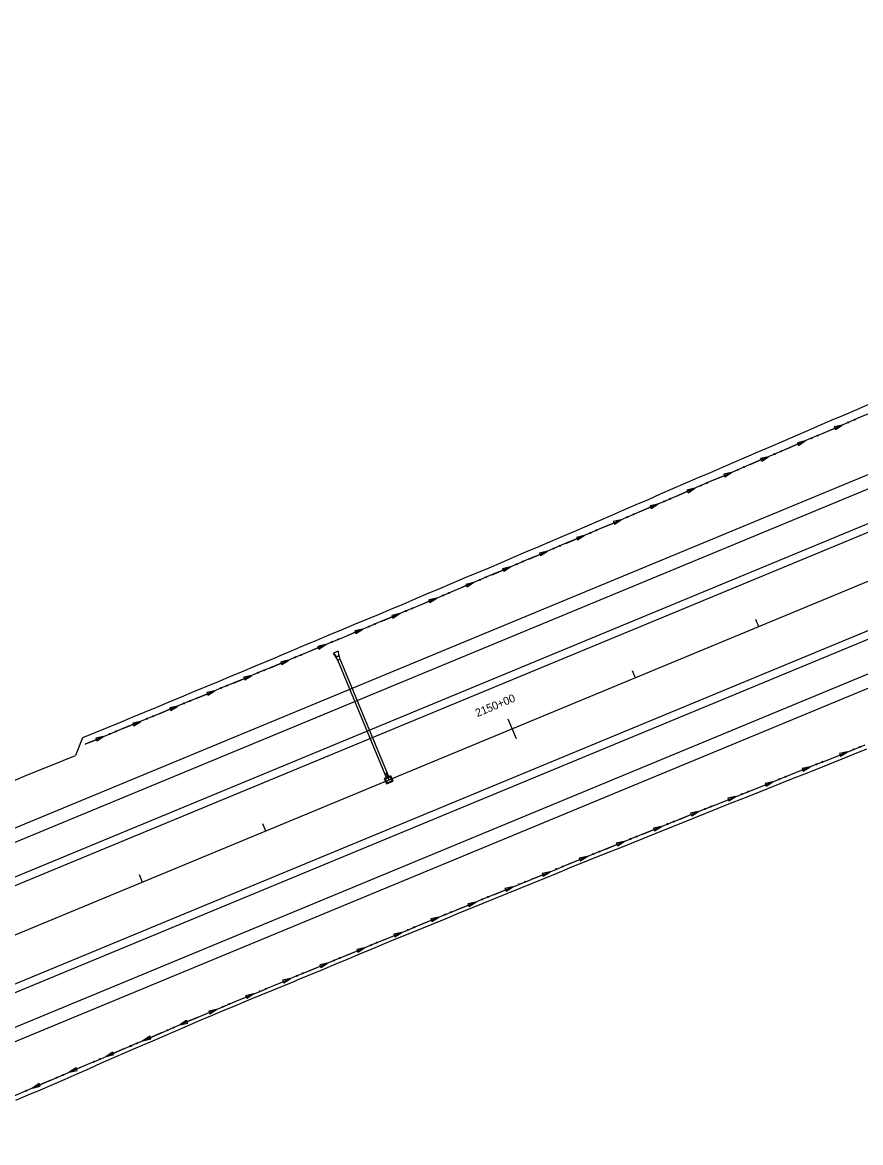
# Model space of a CAD drawing. Extents: x 1611108 to 1749517, y 619561 to 797725.
# Drawn here: x 1720490 to 1721119, y 767471 to 768311 of the extents above; entities that cross this region are included whole.
import ezdxf

# ---------------------------------------------------------------- set-up
doc = ezdxf.new("R2010")
doc.units = 0
for name, color, linetype in [('R_Ditch', 7, 'Continuous'), ('R_Drainage', 7, 'Continuous'), ('R_Horz Alg', 7, 'Continuous'), ('R_Horz Alg Stationing', 7, 'Continuous'), ('R_Proposed Const Limits', 7, 'Continuous'), ('R_Proposed Road', 7, 'Continuous')]:
    doc.layers.add(name, color=color, linetype=linetype)

msp = doc.modelspace()

# ---------------------------------------------------------------- linework, layer by layer
at = {"layer": 'R_Ditch'}
for p, q in [((1721104.89, 768009.2), (1721098.96, 768007.81)), ((1721099.79, 768005.87), (1721104.89, 768009.2)), ((1721098.96, 768007.81), (1721099.79, 768005.87)), ((1721077.28, 767997.38), (1721071.34, 767995.99)), ((1721071.34, 767995.99), (1721072.18, 767994.04)), ((1721072.18, 767994.04), (1721077.28, 767997.38)), ((1721049.66, 767985.55), (1721043.73, 767984.16)), ((1721043.73, 767984.16), (1721044.57, 767982.21)), ((1721044.57, 767982.21), (1721049.66, 767985.55)), ((1721022.05, 767973.72), (1721016.12, 767972.33)), ((1721016.12, 767972.33), (1721016.95, 767970.39)), ((1721016.95, 767970.39), (1721022.05, 767973.72)), ((1720994.44, 767961.89), (1720988.51, 767960.5)), ((1720988.51, 767960.5), (1720989.34, 767958.56)), ((1720989.34, 767958.56), (1720994.44, 767961.89)), ((1720966.83, 767950.07), (1720960.9, 767948.68)), ((1720961.73, 767946.73), (1720966.83, 767950.07)), ((1720960.9, 767948.68), (1720961.73, 767946.73)), ((1720939.22, 767938.24), (1720933.28, 767936.86)), ((1720933.28, 767936.86), (1720934.12, 767934.91)), ((1720934.12, 767934.91), (1720939.22, 767938.24)), ((1720911.59, 767926.44), (1720905.66, 767925.06)), ((1720905.66, 767925.06), (1720906.49, 767923.12)), ((1720906.49, 767923.12), (1720911.59, 767926.44)), ((1720883.96, 767914.68), (1720878.02, 767913.3)), ((1720878.02, 767913.3), (1720878.85, 767911.36)), ((1720878.85, 767911.36), (1720883.96, 767914.68)), ((1720856.31, 767902.94), (1720850.37, 767901.57)), ((1720850.37, 767901.57), (1720851.19, 767899.62)), ((1720851.19, 767899.62), (1720856.31, 767902.94)), ((1720828.64, 767891.23), (1720822.7, 767889.87)), ((1720823.53, 767887.92), (1720828.64, 767891.23)), ((1720822.7, 767889.87), (1720823.53, 767887.92)), ((1720800.97, 767879.55), (1720795.03, 767878.2)), ((1720795.03, 767878.2), (1720795.85, 767876.25)), ((1720795.85, 767876.25), (1720800.97, 767879.55)), ((1720773.28, 767867.9), (1720767.34, 767866.56)), ((1720767.34, 767866.56), (1720768.16, 767864.61)), ((1720768.16, 767864.61), (1720773.28, 767867.9)), ((1720745.58, 767856.29), (1720739.64, 767854.94)), ((1720739.64, 767854.94), (1720740.46, 767852.99)), ((1720740.46, 767852.99), (1720745.58, 767856.29)), ((1720717.87, 767844.7), (1720711.92, 767843.36)), ((1720711.92, 767843.36), (1720712.74, 767841.41)), ((1720712.74, 767841.41), (1720717.87, 767844.7)), ((1720690.14, 767833.14), (1720684.2, 767831.81)), ((1720684.2, 767831.81), (1720685.01, 767829.86)), ((1720685.01, 767829.86), (1720690.14, 767833.14)), ((1720662.41, 767821.61), (1720656.46, 767820.29)), ((1720656.46, 767820.29), (1720657.27, 767818.33)), ((1720657.27, 767818.33), (1720662.41, 767821.61)), ((1720634.66, 767810.11), (1720628.71, 767808.8)), ((1720628.71, 767808.8), (1720629.52, 767806.84)), ((1720629.52, 767806.84), (1720634.66, 767810.11)), ((1720606.89, 767798.64), (1720600.94, 767797.33)), ((1720601.75, 767795.38), (1720606.89, 767798.64)), ((1720600.94, 767797.33), (1720601.75, 767795.38)), ((1720579.12, 767787.2), (1720573.17, 767785.9)), ((1720573.17, 767785.9), (1720573.97, 767783.94)), ((1720573.97, 767783.94), (1720579.12, 767787.2)), ((1720551.33, 767775.8), (1720545.38, 767774.5)), ((1720545.38, 767774.5), (1720546.18, 767772.54)), ((1720546.18, 767772.54), (1720551.33, 767775.8)), ((1721108.82, 767764.25), (1721102.85, 767763.01)), ((1721102.85, 767763.01), (1721103.64, 767761.04)), ((1721103.64, 767761.04), (1721108.82, 767764.25)), ((1721080.93, 767753.09), (1721074.97, 767751.85)), ((1721074.97, 767751.85), (1721075.75, 767749.88)), ((1721075.75, 767749.88), (1721080.93, 767753.09)), ((1721053.04, 767741.93), (1721047.08, 767740.69)), ((1721047.08, 767740.69), (1721047.86, 767738.72)), ((1721047.86, 767738.72), (1721053.04, 767741.93)), ((1721025.16, 767730.77), (1721019.19, 767729.52)), ((1721019.19, 767729.52), (1721019.98, 767727.55)), ((1721019.98, 767727.55), (1721025.16, 767730.77)), ((1720997.28, 767719.58), (1720991.32, 767718.32)), ((1720991.32, 767718.32), (1720992.11, 767716.36)), ((1720992.11, 767716.36), (1720997.28, 767719.58)), ((1720969.42, 767708.35), (1720963.46, 767707.09)), ((1720963.46, 767707.09), (1720964.25, 767705.13)), ((1720964.25, 767705.13), (1720969.42, 767708.35)), ((1720941.57, 767697.1), (1720935.61, 767695.83)), ((1720935.61, 767695.83), (1720936.4, 767693.87)), ((1720936.4, 767693.87), (1720941.57, 767697.1)), ((1720913.73, 767685.82), (1720907.77, 767684.55)), ((1720907.77, 767684.55), (1720908.57, 767682.59)), ((1720908.57, 767682.59), (1720913.73, 767685.82)), ((1720885.9, 767674.51), (1720879.94, 767673.23)), ((1720879.94, 767673.23), (1720880.74, 767671.27)), ((1720880.74, 767671.27), (1720885.9, 767674.51)), ((1720858.09, 767663.17), (1720852.13, 767661.88)), ((1720852.13, 767661.88), (1720852.93, 767659.92)), ((1720852.93, 767659.92), (1720858.09, 767663.17)), ((1720830.28, 767651.8), (1720824.33, 767650.5)), ((1720824.33, 767650.5), (1720825.13, 767648.55)), ((1720825.13, 767648.55), (1720830.28, 767651.8)), ((1720802.49, 767640.4), (1720796.54, 767639.09)), ((1720796.54, 767639.09), (1720797.35, 767637.14)), ((1720797.35, 767637.14), (1720802.49, 767640.4)), ((1720774.72, 767628.97), (1720768.76, 767627.66)), ((1720768.76, 767627.66), (1720769.57, 767625.7)), ((1720769.57, 767625.7), (1720774.72, 767628.97)), ((1720746.95, 767617.5), (1720741, 767616.19)), ((1720741, 767616.19), (1720741.81, 767614.23)), ((1720741.81, 767614.23), (1720746.95, 767617.5)), ((1720719.2, 767606.01), (1720713.25, 767604.69)), ((1720714.06, 767602.74), (1720719.2, 767606.01)), ((1720713.25, 767604.69), (1720714.06, 767602.74)), ((1720691.46, 767594.49), (1720685.51, 767593.16)), ((1720685.51, 767593.16), (1720686.32, 767591.21)), ((1720686.32, 767591.21), (1720691.46, 767594.49)), ((1720663.73, 767582.94), (1720657.78, 767581.6)), ((1720657.78, 767581.6), (1720658.6, 767579.65)), ((1720658.6, 767579.65), (1720663.73, 767582.94)), ((1720636.01, 767571.36), (1720630.07, 767570.02)), ((1720630.07, 767570.02), (1720630.89, 767568.07)), ((1720630.89, 767568.07), (1720636.01, 767571.36)), ((1720613.48, 767563.01), (1720608.38, 767559.68)), ((1720608.38, 767559.68), (1720614.31, 767561.06)), ((1720614.31, 767561.06), (1720613.48, 767563.01)), ((1720585.86, 767551.21), (1720580.76, 767547.87)), ((1720580.76, 767547.87), (1720586.69, 767549.26)), ((1720586.69, 767549.26), (1720585.86, 767551.21)), ((1720558.25, 767539.38), (1720553.15, 767536.04)), ((1720559.08, 767537.43), (1720558.25, 767539.38)), ((1720553.15, 767536.04), (1720559.08, 767537.43)), ((1720530.64, 767527.55), (1720525.54, 767524.22)), ((1720525.54, 767524.22), (1720531.47, 767525.61)), ((1720531.47, 767525.61), (1720530.64, 767527.55)), ((1720503.02, 767515.72), (1720497.93, 767512.39)), ((1720497.93, 767512.39), (1720503.86, 767513.78)), ((1720503.86, 767513.78), (1720503.02, 767515.72))]:
    msp.add_line(p, q, dxfattribs=at)
for points in [[(1721127.19, 768018.76), (1721118, 768014.82), (1721108.8, 768010.88), (1721099.61, 768006.94), (1721090.42, 768003.01), (1721081.23, 767999.07), (1721072.03, 767995.13), (1721062.84, 767991.19), (1721053.65, 767987.25), (1721044.45, 767983.32), (1721035.26, 767979.38), (1721026.07, 767975.44), (1721016.88, 767971.5), (1721007.68, 767967.57), (1720998.49, 767963.63), (1720989.3, 767959.69), (1720980.1, 767955.75), (1720970.91, 767951.82), (1720961.72, 767947.88), (1720952.53, 767943.94), (1720943.33, 767940), (1720934.14, 767936.07), (1720924.94, 767932.14), (1720915.74, 767928.21), (1720906.54, 767924.29), (1720897.34, 767920.37), (1720888.14, 767916.46), (1720878.94, 767912.54), (1720869.73, 767908.64), (1720860.53, 767904.73), (1720851.32, 767900.83), (1720842.11, 767896.93), (1720832.9, 767893.03), (1720823.69, 767889.14), (1720814.48, 767885.25), (1720805.26, 767881.36), (1720796.05, 767877.48), (1720786.83, 767873.6), (1720777.61, 767869.72), (1720768.39, 767865.85), (1720759.17, 767861.98), (1720749.95, 767858.11), (1720740.73, 767854.25), (1720731.5, 767850.39), (1720722.27, 767846.54), (1720713.04, 767842.68), (1720703.82, 767838.83), (1720694.58, 767834.99), (1720685.35, 767831.15), (1720683.46, 767830.36), (1720676.12, 767827.31), (1720666.88, 767823.47), (1720657.65, 767819.64), (1720648.41, 767815.81), (1720639.17, 767811.98), (1720629.93, 767808.16), (1720620.69, 767804.34), (1720611.45, 767800.52), (1720602.2, 767796.71), (1720592.96, 767792.9), (1720583.71, 767789.09), (1720574.46, 767785.29), (1720565.21, 767781.49), (1720555.96, 767777.69), (1720546.71, 767773.9), (1720537.45, 767770.11)], [(1721091.1, 768003.3), (1721099.61, 768006.94), (1721104.89, 768009.2)], [(1721118.68, 768015.11), (1721118.71, 768015.12)], [(1721091.06, 768003.28), (1721091.1, 768003.3)], [(1721063.45, 767991.45), (1721063.49, 767991.47)], [(1721063.49, 767991.47), (1721072.03, 767995.13), (1721077.28, 767997.38)], [(1721035.88, 767979.64), (1721044.45, 767983.32), (1721049.66, 767985.55)], [(1721035.84, 767979.63), (1721035.88, 767979.64)], [(1721008.23, 767967.8), (1721008.26, 767967.82)], [(1721008.26, 767967.82), (1721016.88, 767971.5), (1721022.05, 767973.72)], [(1720980.65, 767955.99), (1720989.3, 767959.69), (1720994.44, 767961.89)], [(1720953.04, 767944.16), (1720961.72, 767947.88), (1720966.83, 767950.07)], [(1720980.62, 767955.97), (1720980.65, 767955.99)], [(1720953.01, 767944.15), (1720953.04, 767944.16)], [(1720925.42, 767932.35), (1720934.14, 767936.07), (1720939.22, 767938.24)], [(1720897.79, 767920.56), (1720906.54, 767924.29), (1720911.59, 767926.44)], [(1720925.39, 767932.33), (1720925.42, 767932.35)], [(1720897.76, 767920.55), (1720897.79, 767920.56)], [(1720870.11, 767908.8), (1720870.15, 767908.81)], [(1720870.15, 767908.81), (1720878.94, 767912.54), (1720883.96, 767914.68)], [(1720842.49, 767897.09), (1720851.32, 767900.83), (1720856.31, 767902.94)], [(1720814.83, 767885.4), (1720823.69, 767889.14), (1720828.64, 767891.23)], [(1720842.46, 767897.07), (1720842.49, 767897.09)], [(1720814.79, 767885.38), (1720814.83, 767885.39)], [(1720787.11, 767873.72), (1720787.14, 767873.73)], [(1720787.14, 767873.73), (1720796.05, 767877.48), (1720800.97, 767879.55)], [(1720759.45, 767862.1), (1720768.39, 767865.85), (1720773.28, 767867.9)], [(1720759.42, 767862.08), (1720759.45, 767862.1)], [(1720731.71, 767850.48), (1720731.74, 767850.49)], [(1720731.74, 767850.49), (1720740.73, 767854.25), (1720745.58, 767856.29)], [(1720704.03, 767838.92), (1720713.04, 767842.68), (1720717.87, 767844.7)], [(1720676.29, 767827.38), (1720683.46, 767830.36), (1720685.35, 767831.15), (1720690.14, 767833.14)], [(1720703.99, 767838.91), (1720704.02, 767838.92)], [(1720676.26, 767827.36), (1720676.29, 767827.38)], [(1720648.52, 767815.85), (1720648.55, 767815.86)], [(1720648.55, 767815.86), (1720657.65, 767819.64), (1720662.41, 767821.61)], [(1720620.79, 767804.38), (1720629.93, 767808.16), (1720634.66, 767810.11)], [(1720593.03, 767792.93), (1720602.2, 767796.71), (1720606.89, 767798.64)], [(1720620.76, 767804.37), (1720620.79, 767804.38)], [(1720592.99, 767792.91), (1720593.03, 767792.93)], [(1720565.21, 767781.49), (1720565.21, 767781.49), (1720565.24, 767781.5)], [(1720565.24, 767781.5), (1720574.46, 767785.29), (1720579.12, 767787.2)], [(1720537.45, 767770.11), (1720546.71, 767773.9), (1720551.33, 767775.8)], [(1720622.18, 767565.56), (1720629.25, 767568.53), (1720631.4, 767569.43), (1720636.4, 767571.52), (1720640.62, 767573.29), (1720649.85, 767577.15), (1720659.08, 767581), (1720668.31, 767584.85), (1720677.54, 767588.7), (1720686.77, 767592.54), (1720693.51, 767595.35), (1720696, 767596.38), (1720705.24, 767600.22), (1720714.47, 767604.05), (1720723.71, 767607.88), (1720732.95, 767611.71), (1720742.19, 767615.54), (1720751.43, 767619.36), (1720752.71, 767619.89), (1720760.67, 767623.17), (1720768.03, 767626.21), (1720769.92, 767626.99), (1720779.16, 767630.8), (1720788.41, 767634.61), (1720797.66, 767638.41), (1720806.91, 767642.21), (1720816.16, 767646.01), (1720825.41, 767649.8), (1720834.66, 767653.59), (1720843.92, 767657.38), (1720853.18, 767661.17), (1720862.43, 767664.95), (1720871.69, 767668.72), (1720880.95, 767672.5), (1720890.22, 767676.27), (1720899.48, 767680.04), (1720908.74, 767683.8), (1720918.01, 767687.56), (1720927.28, 767691.32), (1720936.55, 767695.07), (1720945.82, 767698.82), (1720955.09, 767702.57), (1720964.36, 767706.32), (1720973.64, 767710.06), (1720982.91, 767713.79), (1720992.19, 767717.53), (1721001.47, 767721.26), (1721010.75, 767724.99), (1721020.03, 767728.71), (1721029.31, 767732.43), (1721038.59, 767736.15), (1721047.88, 767739.87), (1721057.16, 767743.58), (1721066.45, 767747.3), (1721075.73, 767751.01), (1721085.02, 767754.73), (1721094.3, 767758.45), (1721103.59, 767762.16), (1721112.87, 767765.88), (1721122.16, 767769.59)], [(1721094.86, 767758.67), (1721094.89, 767758.68)], [(1721094.89, 767758.68), (1721103.59, 767762.16), (1721108.82, 767764.25)], [(1721067, 767747.52), (1721075.73, 767751.01), (1721080.93, 767753.09)], [(1721039.12, 767736.36), (1721047.88, 767739.87), (1721053.04, 767741.93)], [(1721066.97, 767747.51), (1721067, 767747.52)], [(1721039.08, 767736.34), (1721039.12, 767736.36)], [(1721011.2, 767725.17), (1721011.23, 767725.18)], [(1721011.23, 767725.18), (1721020.03, 767728.71), (1721025.16, 767730.77)], [(1720983.36, 767713.98), (1720992.19, 767717.53), (1720997.28, 767719.58)], [(1720955.51, 767702.74), (1720964.36, 767706.32), (1720969.42, 767708.35)], [(1720983.33, 767713.96), (1720983.36, 767713.98)], [(1720955.47, 767702.73), (1720955.51, 767702.74)], [(1720927.63, 767691.46), (1720927.66, 767691.47)], [(1720927.66, 767691.47), (1720936.55, 767695.07), (1720941.57, 767697.1)], [(1720899.83, 767680.18), (1720908.74, 767683.8), (1720913.73, 767685.82)], [(1720872.01, 767668.85), (1720880.95, 767672.5), (1720885.9, 767674.51)], [(1720899.79, 767680.16), (1720899.83, 767680.18)], [(1720871.97, 767668.84), (1720872.01, 767668.85)], [(1720844.16, 767657.48), (1720844.2, 767657.5)], [(1720844.2, 767657.5), (1720853.18, 767661.17), (1720858.09, 767663.17)], [(1720816.4, 767646.11), (1720825.41, 767649.8), (1720830.28, 767651.8)], [(1720788.62, 767634.69), (1720797.66, 767638.41), (1720802.49, 767640.4)], [(1720816.37, 767646.1), (1720816.4, 767646.11)], [(1720788.58, 767634.68), (1720788.62, 767634.69)], [(1720760.81, 767623.23), (1720760.85, 767623.25)], [(1720760.85, 767623.25), (1720768.03, 767626.21), (1720769.92, 767626.99), (1720774.72, 767628.97)], [(1720733.09, 767611.77), (1720742.19, 767615.54), (1720746.95, 767617.5)], [(1720705.34, 767600.26), (1720714.47, 767604.05), (1720719.2, 767606.01)], [(1720733.05, 767611.76), (1720733.09, 767611.77)], [(1720705.31, 767600.25), (1720705.34, 767600.26)], [(1720677.57, 767588.71), (1720677.61, 767588.73)], [(1720677.61, 767588.73), (1720686.77, 767592.54), (1720691.46, 767594.49)], [(1720649.89, 767577.16), (1720659.08, 767581), (1720663.73, 767582.94)], [(1720649.85, 767577.14), (1720649.85, 767577.15), (1720649.89, 767577.16)], [(1720484.27, 767506.54), (1720493.46, 767510.48), (1720502.65, 767514.42), (1720511.84, 767518.35), (1720521.04, 767522.29), (1720530.23, 767526.23), (1720539.42, 767530.17), (1720548.62, 767534.1), (1720557.81, 767538.04), (1720567, 767541.98), (1720576.2, 767545.92), (1720585.39, 767549.85), (1720594.58, 767553.79), (1720603.78, 767557.71), (1720612.98, 767561.64), (1720622.18, 767565.56)], [(1720622.18, 767565.56), (1720612.98, 767561.64), (1720608.38, 767559.68)], [(1720622.18, 767565.56), (1720629.25, 767568.53), (1720631.4, 767569.43), (1720636.01, 767571.36)], [(1720594.55, 767553.77), (1720585.39, 767549.85), (1720580.76, 767547.87)], [(1720594.59, 767553.79), (1720594.58, 767553.79), (1720594.55, 767553.77)], [(1720566.94, 767541.95), (1720557.81, 767538.04), (1720553.15, 767536.04)], [(1720566.97, 767541.97), (1720566.94, 767541.95)], [(1720539.32, 767530.12), (1720530.23, 767526.23), (1720525.54, 767524.22)], [(1720539.36, 767530.14), (1720539.33, 767530.12)], [(1720511.71, 767518.3), (1720502.65, 767514.42), (1720497.93, 767512.39)], [(1720511.75, 767518.31), (1720511.71, 767518.3)]]:
    msp.add_lwpolyline(points, dxfattribs=at)
for centre in [(1721109.47, 768011.21), (1721114.08, 768013.18), (1721081.86, 767999.38), (1721086.47, 768001.35), (1721054.25, 767987.55), (1721058.86, 767989.53), (1721026.64, 767975.73), (1721031.25, 767977.7), (1721003.63, 767965.87), (1720999.03, 767963.9), (1720971.42, 767952.07), (1720976.02, 767954.04), (1720948.41, 767942.22), (1720943.8, 767940.24), (1720916.18, 767928.44), (1720920.79, 767930.41), (1720888.55, 767916.67), (1720893.16, 767918.63), (1720860.9, 767904.93), (1720865.51, 767906.88), (1720833.24, 767893.21), (1720837.85, 767895.16), (1720810.18, 767883.48), (1720805.57, 767881.53), (1720777.88, 767869.88), (1720782.5, 767871.82), (1720750.18, 767858.25), (1720754.81, 767860.19), (1720727.1, 767848.59), (1720722.47, 767846.66), (1720694.75, 767835.1), (1720699.38, 767837.02), (1720667.02, 767823.56), (1720671.64, 767825.48), (1720639.27, 767812.06), (1720643.9, 767813.98), (1720611.51, 767800.59), (1720616.14, 767802.5), (1720588.37, 767791.05), (1720583.73, 767789.14), (1720555.95, 767777.73), (1720560.58, 767779.63), (1721113.45, 767766.15), (1721118.1, 767768.01), (1721090.21, 767756.85), (1721085.56, 767754.99), (1721057.68, 767743.83), (1721062.33, 767745.69), (1721029.79, 767732.66), (1721034.44, 767734.53), (1721006.56, 767723.34), (1721001.91, 767721.48), (1720974.05, 767710.26), (1720978.69, 767712.13), (1720946.19, 767699.02), (1720950.84, 767700.89), (1720922.99, 767689.62), (1720918.35, 767687.74), (1720890.52, 767676.43), (1720895.16, 767678.32), (1720862.71, 767665.1), (1720867.34, 767666.99), (1720839.54, 767655.63), (1720834.9, 767653.73), (1720807.11, 767642.33), (1720811.74, 767644.24), (1720779.33, 767630.91), (1720783.96, 767632.81), (1720751.56, 767619.45), (1720756.19, 767621.36), (1720723.81, 767607.96), (1720728.44, 767609.88), (1720696.06, 767596.45), (1720700.69, 767598.37), (1720668.33, 767584.9), (1720672.96, 767586.83), (1720640.62, 767573.32), (1720645.24, 767575.26), (1720599.18, 767555.71), (1720603.79, 767557.68), (1720571.57, 767543.89), (1720576.17, 767545.87), (1720543.96, 767532.07), (1720548.56, 767534.04), (1720520.95, 767522.21), (1720516.34, 767520.24), (1720493.34, 767510.39)]:
    msp.add_circle(centre, 0.375, dxfattribs=at)
at = {"layer": 'R_Drainage'}
for p, q in [((1720727.21, 767839.84), (1720723.52, 767838.31)), ((1720726.78, 767833.04), (1720723.52, 767838.31)), ((1720723.52, 767838.31), (1720725.41, 767836.06)), ((1720728.63, 767833.8), (1720726.78, 767833.04)), ((1720763.52, 767744.35), (1720726.78, 767833.04)), ((1720728.63, 767833.8), (1720727.21, 767839.84)), ((1720727.21, 767839.84), (1720727.46, 767836.91)), ((1720765.37, 767745.11), (1720728.63, 767833.8))]:
    msp.add_line(p, q, dxfattribs=at)
for points in [[(1720761.72, 767744.32), (1720763.38, 767740.32), (1720768.31, 767742.36), (1720766.65, 767746.37)], [(1720762.59, 767743.96), (1720763.74, 767741.19), (1720767.44, 767742.72), (1720766.29, 767745.49)]]:
    msp.add_lwpolyline(points, close=True, dxfattribs=at)
msp.add_arc((1720726.3, 767836.81), 1.17, 220.02993, 4.97008, dxfattribs=at)
at = {"layer": 'R_Horz Alg'}
msp.add_line((1715964.86, 765755.05), (1723860.62, 769025.58), dxfattribs=at)
at = {"layer": 'R_Horz Alg Stationing'}
for points in [[(1721039.88, 767863.69), (1721042.18, 767858.15)], [(1720947.5, 767825.42), (1720949.79, 767819.88)], [(1720854.34, 767789), (1720860.47, 767774.22)], [(1720762.72, 767748.89), (1720765.02, 767743.34)], [(1720670.33, 767710.62), (1720672.63, 767705.08)], [(1720577.94, 767672.35), (1720580.24, 767666.81)]]:
    msp.add_lwpolyline(points, dxfattribs=at)
at = {"layer": 'R_Proposed Const Limits'}
msp.add_line((1720535.47, 767774.9), (1720530.12, 767761.67), dxfattribs=at)
for points in [[(1721124.73, 768024.7), (1721115.54, 768020.74), (1721106.37, 768016.76), (1721097.19, 768012.79), (1721088.01, 768008.82), (1721078.83, 768004.84), (1721069.65, 768000.88), (1721060.46, 767996.94), (1721051.27, 767992.99), (1721042.08, 767989.05), (1721032.88, 767985.12), (1721023.7, 767981.15), (1721014.54, 767977.14), (1721005.38, 767973.13), (1720996.11, 767969.38), (1720986.93, 767965.41), (1720977.75, 767961.43), (1720968.57, 767957.46), (1720959.49, 767953.26), (1720950.29, 767949.34), (1720941.09, 767945.42), (1720931.9, 767941.47), (1720922.72, 767937.49), (1720913.55, 767933.52), (1720904.37, 767929.55), (1720895.18, 767925.6), (1720885.98, 767921.68), (1720876.77, 767917.78), (1720867.56, 767913.87), (1720858.39, 767909.89), (1720849.22, 767905.9), (1720840, 767902.02), (1720830.74, 767898.25), (1720821.49, 767894.44), (1720812.29, 767890.52), (1720803.1, 767886.59), (1720793.9, 767882.67), (1720784.7, 767878.76), (1720775.49, 767874.84), (1720766.29, 767870.93), (1720757.08, 767867.02), (1720747.85, 767863.19), (1720738.59, 767859.4), (1720729.37, 767855.54), (1720720.14, 767851.68), (1720710.92, 767847.82), (1720701.7, 767843.94), (1720692.49, 767840.05), (1720683.27, 767836.17), (1720681.39, 767835.37), (1720674.06, 767832.28), (1720664.81, 767828.46), (1720655.58, 767824.63), (1720646.35, 767820.77), (1720637.13, 767816.92), (1720627.9, 767813.07), (1720618.66, 767809.23), (1720609.43, 767805.38), (1720600.21, 767801.53), (1720590.98, 767797.68), (1720581.75, 767793.83), (1720572.52, 767789.98), (1720563.28, 767786.16), (1720554.03, 767782.35), (1720544.72, 767778.7), (1720535.47, 767774.9)], [(1720485.63, 767503.26), (1720494.82, 767507.2), (1720504.01, 767511.15), (1720513.19, 767515.11), (1720522.37, 767519.08), (1720531.53, 767523.09), (1720540.68, 767527.14), (1720549.82, 767531.19), (1720558.97, 767535.24), (1720568.15, 767539.21), (1720577.34, 767543.16), (1720586.52, 767547.12), (1720595.71, 767551.06), (1720604.9, 767555.01), (1720614.09, 767558.95), (1720623.27, 767562.92), (1720630.33, 767565.9), (1720632.49, 767566.81), (1720637.48, 767568.91), (1720641.7, 767570.69), (1720650.92, 767574.57), (1720660.14, 767578.44), (1720669.41, 767582.18), (1720678.64, 767586.04), (1720687.89, 767589.83), (1720694.66, 767592.59), (1720697.15, 767593.61), (1720706.4, 767597.42), (1720715.64, 767601.24), (1720724.85, 767605.13), (1720734.06, 767609.02), (1720743.28, 767612.91), (1720752.49, 767616.8), (1720753.77, 767617.33), (1720761.74, 767620.59), (1720769.1, 767623.62), (1720770.99, 767624.39), (1720780.24, 767628.19), (1720789.5, 767631.98), (1720798.75, 767635.77), (1720808, 767639.56), (1720817.25, 767643.37), (1720826.51, 767647.15), (1720835.77, 767650.94), (1720845.02, 767654.71), (1720854.29, 767658.49), (1720863.55, 767662.25), (1720872.81, 767666.02), (1720882.08, 767669.78), (1720891.35, 767673.52), (1720900.62, 767677.29), (1720909.88, 767681.07), (1720919.15, 767684.81), (1720928.43, 767688.53), (1720937.72, 767692.24), (1720946.99, 767695.98), (1720956.27, 767699.73), (1720965.54, 767703.47), (1720974.81, 767707.21), (1720984.1, 767710.93), (1720993.37, 767714.68), (1721002.66, 767718.39), (1721011.95, 767722.08), (1721021.24, 767725.78), (1721030.54, 767729.47), (1721039.83, 767733.17), (1721049.11, 767736.89), (1721058.4, 767740.6), (1721067.69, 767744.3), (1721077.01, 767747.94), (1721086.3, 767751.64), (1721095.58, 767755.37), (1721104.85, 767759.1), (1721114.13, 767762.83), (1721123.42, 767766.55)], [(1720483.85, 767742.73), (1720493.11, 767746.51), (1720502.36, 767750.3), (1720511.62, 767754.09), (1720520.87, 767757.88), (1720530.12, 767761.67)]]:
    msp.add_lwpolyline(points, dxfattribs=at)
at = {"layer": 'R_Proposed Road'}
for p, q in [((1715936.54, 765823.42), (1723832.3, 769093.95)), ((1715940.37, 765814.18), (1723836.12, 769084.71)), ((1715949.55, 765792.01), (1723845.31, 769062.54)), ((1715951.85, 765786.47), (1723847.6, 769056.99)), ((1715977.87, 765723.64), (1723873.63, 768994.17)), ((1715980.17, 765718.1), (1723875.92, 768988.63)), ((1715989.35, 765695.93), (1723885.11, 768966.45)), ((1715993.18, 765686.69), (1723888.93, 768957.22))]:
    msp.add_line(p, q, dxfattribs=at)

# ---------------------------------------------------------------- texts
at = {"layer": 'R_Horz Alg Stationing'}
msp.add_text('2150+00', height=6, rotation=22.5, dxfattribs=at).set_placement((1720831.44, 767790.34))

doc.saveas('drawing.dxf')
